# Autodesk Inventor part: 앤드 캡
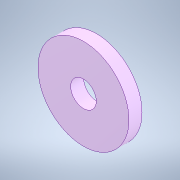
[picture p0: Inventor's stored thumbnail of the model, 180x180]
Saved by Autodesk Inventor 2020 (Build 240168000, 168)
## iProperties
Created: 2024-04
Part Number: 앤드 캡
Material: 강철, 연강
Document SubType Name: Modeling
Designer: oem
Density: 7.86 g/cm^3
Appearance: 기본값
Author: jhkim
Sending System: Autodesk Inventor 2025
Preprocessor: ST-DEVELOPER v20
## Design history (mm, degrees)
feature "솔리드1"
node "솔리드2"
